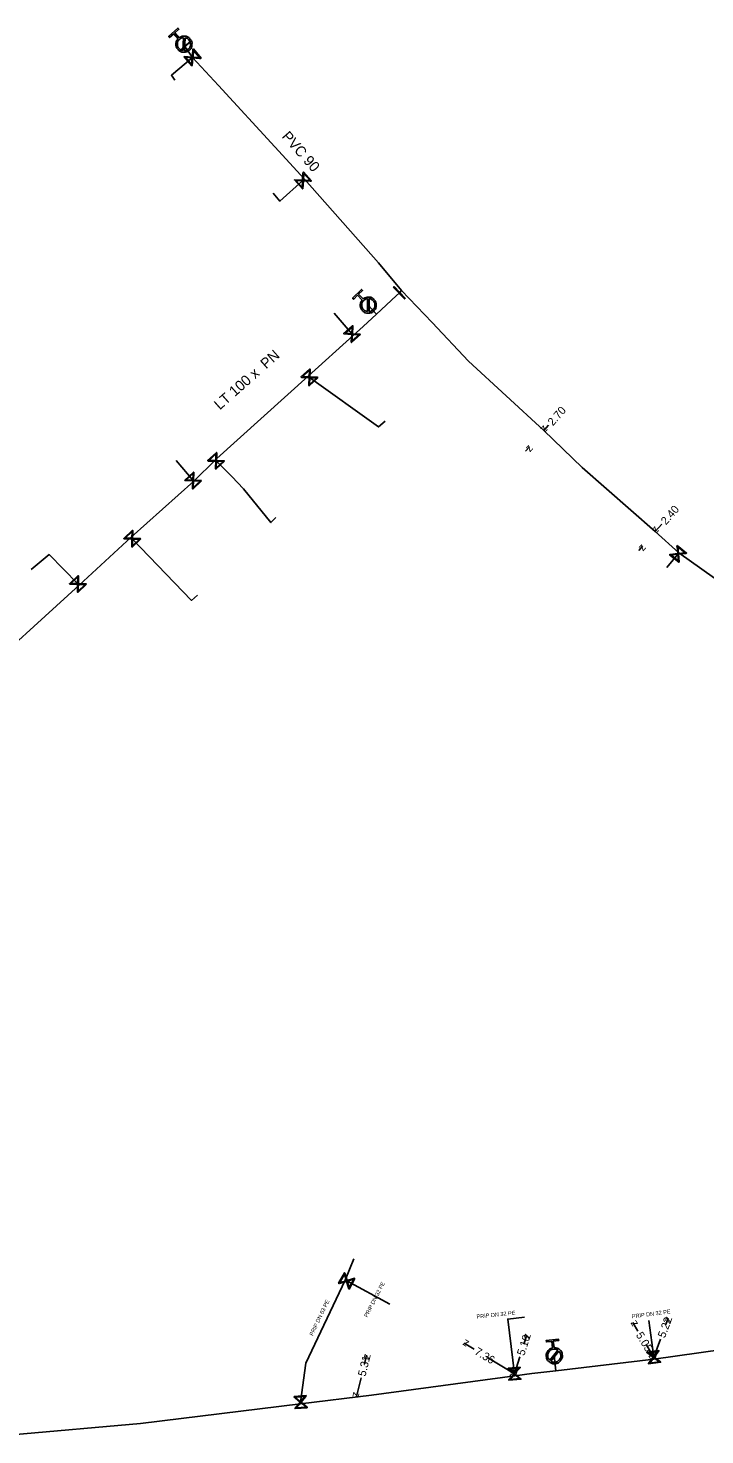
# Model space of a CAD drawing. Extents: x -643842 to -636370, y -1119190 to -1110210.
# Drawn here: x -642219.1 to -642134.5, y -1115188.5 to -1115012.7 of the extents above; entities that cross this region are included whole.
import ezdxf

# ---------------------------------------------------------------- set-up
doc = ezdxf.new("R2010")
doc.units = 0
for name, color, linetype in [('22', 7, 'Continuous'), ('Default', 7, 'Continuous'), ('Level 10', 7, 'Continuous'), ('Level 16', 7, 'Continuous'), ('Level 20', 7, 'Continuous'), ('Level 21', 7, 'Continuous'), ('Level 23', 7, 'Continuous'), ('Level 33', 7, 'Continuous')]:
    doc.layers.add(name, color=color, linetype=linetype)

msp = doc.modelspace()

# ---------------------------------------------------------------- linework, layer by layer
at = {"layer": 'Default'}
for points in [[(-642200.2, -1115013.9), (-642199.91, -1115013.68), (-642199.55, -1115013.7), (-642199.13, -1115013.72), (-642198.86, -1115014.03), (-642198.58, -1115014.34), (-642198.6, -1115014.75), (-642198.62, -1115015.17), (-642198.93, -1115015.44), (-642199.24, -1115015.72), (-642199.65, -1115015.7), (-642200.06, -1115015.68), (-642200.34, -1115015.37), (-642200.62, -1115015.06), (-642200.6, -1115014.65), (-642200.58, -1115014.28), (-642200.34, -1115014.02)], [(-642199.65, -1115013.89), (-642199.93, -1115013.9), (-642200.15, -1115014.1), (-642200.4, -1115014.32), (-642200.42, -1115014.66), (-642200.43, -1115014.99), (-642200.21, -1115015.24), (-642200.01, -1115015.46), (-642199.73, -1115015.5)], [(-642199.55, -1115015.51), (-642199.27, -1115015.5), (-642199.06, -1115015.3), (-642198.81, -1115015.08), (-642198.79, -1115014.74), (-642198.77, -1115014.41), (-642199, -1115014.16), (-642199.19, -1115013.94), (-642199.47, -1115013.9)], [(-642177.19, -1115046.54), (-642176.92, -1115046.31), (-642176.55, -1115046.31), (-642176.14, -1115046.31), (-642175.85, -1115046.61), (-642175.56, -1115046.9), (-642175.56, -1115047.32), (-642175.56, -1115047.73), (-642175.86, -1115048.02), (-642176.15, -1115048.31), (-642176.56, -1115048.31), (-642176.98, -1115048.31), (-642177.27, -1115048.02), (-642177.56, -1115047.72), (-642177.56, -1115047.31), (-642177.56, -1115046.94), (-642177.33, -1115046.67)], [(-642176.65, -1115046.5), (-642176.93, -1115046.53), (-642177.13, -1115046.73), (-642177.37, -1115046.97), (-642177.38, -1115047.31), (-642177.38, -1115047.64), (-642177.14, -1115047.88), (-642176.93, -1115048.09), (-642176.66, -1115048.12)], [(-642176.47, -1115048.12), (-642176.2, -1115048.09), (-642175.99, -1115047.89), (-642175.75, -1115047.65), (-642175.75, -1115047.32), (-642175.75, -1115046.98), (-642175.98, -1115046.74), (-642176.19, -1115046.53), (-642176.46, -1115046.5)], [(-642153.35, -1115177.6), (-642152.99, -1115177.59), (-642152.7, -1115177.81), (-642152.37, -1115178.07), (-642152.32, -1115178.48), (-642152.27, -1115178.89), (-642152.53, -1115179.22), (-642152.78, -1115179.54), (-642153.19, -1115179.59), (-642153.6, -1115179.64), (-642153.93, -1115179.39), (-642154.26, -1115179.14), (-642154.31, -1115178.73), (-642154.36, -1115178.31), (-642154.11, -1115177.99), (-642153.88, -1115177.7), (-642153.53, -1115177.62)], [(-642152.89, -1115177.91), (-642153.13, -1115177.76), (-642153.42, -1115177.79), (-642153.75, -1115177.83), (-642153.96, -1115178.1), (-642154.17, -1115178.36), (-642154.12, -1115178.7), (-642154.09, -1115178.99), (-642153.89, -1115179.18)], [(-642153.74, -1115179.3), (-642153.5, -1115179.44), (-642153.22, -1115179.41), (-642152.88, -1115179.36), (-642152.68, -1115179.1), (-642152.47, -1115178.83), (-642152.51, -1115178.5), (-642152.55, -1115178.21), (-642152.75, -1115178.02)]]:
    msp.add_open_spline(points, degree=3, dxfattribs=at)
at = {"layer": 'Level 10'}
for points in [[(-642154.03, -1115062.33), (-642154.62, -1115062.99)], [(-642156.9, -1115065.58), (-642156.4, -1115065.02)], [(-642139.89, -1115074.7), (-642140.7, -1115075.62)], [(-642142.77, -1115077.98), (-642142.28, -1115077.42)], [(-642139.37, -1115174.71), (-642139.07, -1115173.9)], [(-642157.11, -1115177.15), (-642156.74, -1115176)], [(-642142.86, -1115175.54), (-642143.51, -1115174.47)], [(-642163.33, -1115177.79), (-642164.58, -1115177.03)], [(-642141.84, -1115177.22), (-642140.89, -1115178.79)], [(-642140.04, -1115176.52), (-642140.89, -1115178.79)], [(-642177.04, -1115179.63), (-642176.77, -1115178.54)], [(-642161.66, -1115178.81), (-642158.29, -1115180.86)], [(-642157.62, -1115178.76), (-642158.29, -1115180.86)], [(-642177.46, -1115181.38), (-642178.03, -1115183.7)]]:
    msp.add_lwpolyline(points, dxfattribs=at)
at = {"layer": 'Level 16'}
for points in [[(-642198.9, -1115014.51), (-642200.02, -1115015.52), (-642200.08, -1115015.45), (-642198.96, -1115014.44), (-642198.9, -1115014.51)], [(-642198.43, -1115015.29), (-642197.47, -1115016.44), (-642197.52, -1115016.49), (-642197.64, -1115016.47), (-642198.48, -1115016.4), (-642198.56, -1115017.36), (-642198.61, -1115017.41), (-642199.58, -1115016.26), (-642199.53, -1115016.22), (-642198.56, -1115016.3), (-642198.49, -1115015.47), (-642198.48, -1115015.34), (-642198.43, -1115015.29)], [(-642198.4, -1115015.47), (-642198.47, -1115016.31), (-642197.64, -1115016.38), (-642198.4, -1115015.47)], [(-642198.64, -1115017.23), (-642198.57, -1115016.39), (-642199.41, -1115016.32), (-642198.64, -1115017.23)], [(-642184.67, -1115030.67), (-642183.67, -1115031.78), (-642183.72, -1115031.82), (-642183.84, -1115031.81), (-642184.68, -1115031.77), (-642184.73, -1115032.74), (-642184.78, -1115032.79), (-642185.79, -1115031.67), (-642185.74, -1115031.63), (-642184.77, -1115031.68), (-642184.73, -1115030.84), (-642184.72, -1115030.71), (-642184.67, -1115030.67)], [(-642184.81, -1115032.61), (-642184.77, -1115031.77), (-642185.61, -1115031.73), (-642184.81, -1115032.61)], [(-642184.64, -1115030.85), (-642184.68, -1115031.69), (-642183.84, -1115031.73), (-642184.64, -1115030.85)], [(-642173.32, -1115045), (-642171.95, -1115046.45), (-642172.04, -1115046.54), (-642173.41, -1115045.09), (-642173.32, -1115045)], [(-642177.53, -1115051), (-642178.66, -1115051.99), (-642178.7, -1115051.94), (-642178.69, -1115051.81), (-642178.64, -1115050.97), (-642179.6, -1115050.91), (-642179.65, -1115050.86), (-642178.52, -1115049.87), (-642178.48, -1115049.92), (-642178.54, -1115050.89), (-642177.7, -1115050.94), (-642177.57, -1115050.95), (-642177.53, -1115051)], [(-642179.47, -1115050.83), (-642178.63, -1115050.89), (-642178.58, -1115050.05), (-642179.47, -1115050.83)], [(-642177.71, -1115051.03), (-642178.55, -1115050.98), (-642178.6, -1115051.81), (-642177.71, -1115051.03)], [(-642182.86, -1115056.38), (-642183.96, -1115057.4), (-642184.01, -1115057.35), (-642184, -1115057.22), (-642183.96, -1115056.38), (-642184.93, -1115056.34), (-642184.98, -1115056.29), (-642183.87, -1115055.28), (-642183.83, -1115055.33), (-642183.87, -1115056.3), (-642183.03, -1115056.33), (-642182.9, -1115056.33), (-642182.86, -1115056.38)], [(-642184.8, -1115056.26), (-642183.96, -1115056.29), (-642183.93, -1115055.45), (-642184.8, -1115056.26)], [(-642183.04, -1115056.42), (-642183.87, -1115056.39), (-642183.91, -1115057.22), (-642183.04, -1115056.42)], [(-642194.52, -1115066.8), (-642195.61, -1115067.83), (-642195.65, -1115067.78), (-642195.65, -1115067.65), (-642195.62, -1115066.81), (-642196.59, -1115066.79), (-642196.64, -1115066.74), (-642195.55, -1115065.71), (-642195.51, -1115065.76), (-642195.53, -1115066.73), (-642194.69, -1115066.75), (-642194.56, -1115066.75), (-642194.52, -1115066.8)], [(-642196.46, -1115066.71), (-642195.62, -1115066.73), (-642195.6, -1115065.89), (-642196.46, -1115066.71)], [(-642194.7, -1115066.84), (-642195.54, -1115066.82), (-642195.56, -1115067.65), (-642194.7, -1115066.84)], [(-642197.39, -1115069.27), (-642198.49, -1115070.29), (-642198.54, -1115070.24), (-642198.53, -1115070.11), (-642198.5, -1115069.27), (-642199.47, -1115069.24), (-642199.51, -1115069.19), (-642198.41, -1115068.17), (-642198.36, -1115068.22), (-642198.4, -1115069.19), (-642197.56, -1115069.22), (-642197.44, -1115069.22), (-642197.39, -1115069.27)], [(-642199.33, -1115069.15), (-642198.49, -1115069.19), (-642198.46, -1115068.35), (-642199.33, -1115069.15)], [(-642197.57, -1115069.31), (-642198.41, -1115069.28), (-642198.44, -1115070.11), (-642197.57, -1115069.31)], [(-642205, -1115076.52), (-642206.09, -1115077.56), (-642206.13, -1115077.51), (-642206.13, -1115077.38), (-642206.11, -1115076.54), (-642207.08, -1115076.52), (-642207.12, -1115076.47), (-642206.04, -1115075.44), (-642205.99, -1115075.48), (-642206.02, -1115076.45), (-642205.18, -1115076.47), (-642205.05, -1115076.47), (-642205, -1115076.52)], [(-642206.95, -1115076.43), (-642206.11, -1115076.45), (-642206.09, -1115075.61), (-642206.95, -1115076.43)], [(-642205.18, -1115076.56), (-642206.02, -1115076.54), (-642206.04, -1115077.38), (-642205.18, -1115076.56)], [(-642137.95, -1115077.34), (-642136.78, -1115078.29), (-642136.83, -1115078.34), (-642136.95, -1115078.35), (-642137.79, -1115078.44), (-642137.69, -1115079.4), (-642137.73, -1115079.45), (-642138.9, -1115078.51), (-642138.85, -1115078.46), (-642137.89, -1115078.36), (-642137.97, -1115077.52), (-642137.99, -1115077.4), (-642137.95, -1115077.34)], [(-642137.89, -1115077.52), (-642137.8, -1115078.35), (-642136.97, -1115078.26), (-642137.89, -1115077.52)], [(-642137.79, -1115079.29), (-642137.88, -1115078.45), (-642138.71, -1115078.53), (-642137.79, -1115079.29)], [(-642211.79, -1115082.19), (-642212.88, -1115083.22), (-642212.92, -1115083.17), (-642212.92, -1115083.04), (-642212.9, -1115082.2), (-642213.87, -1115082.18), (-642213.91, -1115082.13), (-642212.82, -1115081.1), (-642212.78, -1115081.15), (-642212.8, -1115082.12), (-642211.96, -1115082.14), (-642211.84, -1115082.14), (-642211.79, -1115082.19)], [(-642213.74, -1115082.1), (-642212.89, -1115082.12), (-642212.87, -1115081.28), (-642213.74, -1115082.1)], [(-642211.97, -1115082.23), (-642212.81, -1115082.21), (-642212.83, -1115083.04), (-642211.97, -1115082.23)], [(-642178.23, -1115168.95), (-642178.95, -1115170.28), (-642179, -1115170.24), (-642179.04, -1115170.12), (-642179.28, -1115169.32), (-642180.21, -1115169.6), (-642180.27, -1115169.56), (-642179.55, -1115168.24), (-642179.5, -1115168.27), (-642179.22, -1115169.21), (-642178.42, -1115168.96), (-642178.29, -1115168.92), (-642178.23, -1115168.95)], [(-642180.11, -1115169.47), (-642179.3, -1115169.23), (-642179.55, -1115168.43), (-642180.11, -1115169.47)], [(-642178.39, -1115169.05), (-642179.19, -1115169.29), (-642178.95, -1115170.09), (-642178.39, -1115169.05)], [(-642141.74, -1115178.15), (-642140.25, -1115177.94), (-642140.24, -1115178.01), (-642140.32, -1115178.11), (-642140.83, -1115178.78), (-642140.05, -1115179.36), (-642140.04, -1115179.43), (-642141.53, -1115179.64), (-642141.54, -1115179.57), (-642140.95, -1115178.8), (-642141.62, -1115178.29), (-642141.73, -1115178.22), (-642141.74, -1115178.15)], [(-642141.57, -1115178.22), (-642140.9, -1115178.73), (-642140.39, -1115178.06), (-642141.57, -1115178.22)], [(-642140.21, -1115179.36), (-642140.88, -1115178.85), (-642141.38, -1115179.52), (-642140.21, -1115179.36)], [(-642159.1, -1115180.17), (-642157.6, -1115180.05), (-642157.6, -1115180.12), (-642157.68, -1115180.21), (-642158.23, -1115180.85), (-642157.49, -1115181.48), (-642157.48, -1115181.55), (-642158.98, -1115181.67), (-642158.98, -1115181.6), (-642158.35, -1115180.86), (-642158.99, -1115180.32), (-642159.09, -1115180.24), (-642159.1, -1115180.17)], [(-642158.93, -1115180.25), (-642158.29, -1115180.8), (-642157.75, -1115180.16), (-642158.93, -1115180.25)], [(-642157.64, -1115181.47), (-642158.28, -1115180.92), (-642158.83, -1115181.56), (-642157.64, -1115181.47)], [(-642185.83, -1115183.72), (-642184.33, -1115183.6), (-642184.33, -1115183.67), (-642184.41, -1115183.76), (-642184.96, -1115184.4), (-642184.22, -1115185.03), (-642184.21, -1115185.1), (-642185.71, -1115185.22), (-642185.71, -1115185.15), (-642185.08, -1115184.41), (-642185.72, -1115183.87), (-642185.82, -1115183.79), (-642185.83, -1115183.72)], [(-642185.66, -1115183.8), (-642185.02, -1115184.35), (-642184.48, -1115183.71), (-642185.66, -1115183.8)], [(-642184.37, -1115185.02), (-642185.01, -1115184.47), (-642185.56, -1115185.11), (-642184.37, -1115185.02)]]:
    msp.add_lwpolyline(points, dxfattribs=at)
at = {"layer": 'Level 21'}
for points in [[(-642198.52, -1115016.35), (-642195.28, -1115019.88), (-642188.24, -1115027.53), (-642184.54, -1115031.55), (-642175.29, -1115042.01), (-642172.41, -1115045.49)], [(-642226.44, -1115094.82), (-642212.72, -1115082.29), (-642206.19, -1115076.32), (-642198.38, -1115069.31), (-642195.67, -1115066.64), (-642195.5, -1115066.48), (-642184.07, -1115056.18), (-642178.44, -1115051.11), (-642177.21, -1115050), (-642175.54, -1115048.45), (-642173.06, -1115046.13), (-642172.68, -1115045.77), (-642172.41, -1115045.49)], [(-642096.47, -1115104.33), (-642099.41, -1115102.55), (-642107.92, -1115097.4), (-642112.86, -1115094.41), (-642116.46, -1115092.07), (-642120.42, -1115089.63), (-642126.07, -1115086.15), (-642130.4, -1115083.48), (-642137.77, -1115078.28), (-642140.7, -1115075.62), (-642149.85, -1115067.62), (-642154.62, -1115062.99), (-642164.03, -1115054.31), (-642168.6, -1115049.5), (-642172.41, -1115045.49)], [(-641973.55, -1115156.85), (-641975.56, -1115157.26), (-641999.1, -1115160.18), (-642022.03, -1115163.25), (-642035.96, -1115165.14), (-642057.58, -1115168.08), (-642083.46, -1115171.53), (-642087.27, -1115172.03), (-642105.03, -1115174.46), (-642122.74, -1115176.48), (-642123.7, -1115176.62), (-642140.86, -1115179.04), (-642153.13, -1115180.49), (-642156.12, -1115180.85), (-642158.26, -1115181.11), (-642176.15, -1115183.52), (-642185.05, -1115184.62), (-642205.03, -1115187.09), (-642221.08, -1115188.5), (-642223.2, -1115186.19), (-642228.27, -1115181.15), (-642229.1, -1115180.38), (-642229.73, -1115179.82)]]:
    msp.add_lwpolyline(points, dxfattribs=at)
at = {"layer": 'Level 23'}
for points in [[(-642198.52, -1115016.35), (-642199.49, -1115014.98), (-642199.6, -1115014.7)], [(-642198.52, -1115016.35), (-642201.18, -1115018.58), (-642200.76, -1115019.19)], [(-642184.54, -1115031.55), (-642184.73, -1115031.73), (-642187.6, -1115034.33), (-642188.46, -1115033.32)], [(-642176.56, -1115047.31), (-642175.54, -1115048.45)], [(-642178.44, -1115051.11), (-642178.59, -1115050.93), (-642180.83, -1115048.33)], [(-642184.07, -1115056.18), (-642183.92, -1115056.34), (-642175.27, -1115062.53), (-642174.44, -1115061.8)], [(-642198.38, -1115069.31), (-642198.45, -1115069.23), (-642200.59, -1115066.74)], [(-642195.67, -1115066.64), (-642195.58, -1115066.77), (-642193.62, -1115068.73), (-642192.14, -1115070.27), (-642188.73, -1115074.48), (-642188.1, -1115073.85)], [(-642206.19, -1115076.32), (-642206.06, -1115076.5), (-642198.65, -1115084.21), (-642197.92, -1115083.56)], [(-642212.72, -1115082.29), (-642212.85, -1115082.16), (-642216.43, -1115078.49), (-642218.71, -1115080.33)], [(-642137.77, -1115078.28), (-642137.84, -1115078.4), (-642139.25, -1115080.08)], [(-642178.36, -1115166.5), (-642179.45, -1115169.15), (-642184.38, -1115179.54), (-642185.02, -1115184.41), (-642185.05, -1115184.62)], [(-642179.45, -1115169.15), (-642179.25, -1115169.26), (-642173.86, -1115172.16)], [(-642158.26, -1115181.11), (-642158.29, -1115180.86), (-642159.14, -1115174.03), (-642157.02, -1115173.81)], [(-642140.86, -1115179.04), (-642140.89, -1115178.79), (-642141.49, -1115174.21)], [(-642153.32, -1115178.6), (-642153.13, -1115180.49)]]:
    msp.add_lwpolyline(points, dxfattribs=at)
at = {"layer": 'Level 33'}
for points in [[(-642200.34, -1115014.02), (-642200.88, -1115013.41), (-642201.4, -1115013.88), (-642201.52, -1115013.74), (-642200.36, -1115012.69), (-642200.24, -1115012.83), (-642200.75, -1115013.29), (-642200.2, -1115013.9)], [(-642199.73, -1115015.5), (-642199.65, -1115013.89)], [(-642199.47, -1115013.9), (-642199.55, -1115015.51)], [(-642177.33, -1115046.67), (-642177.9, -1115046.08), (-642178.39, -1115046.57), (-642178.52, -1115046.44), (-642177.41, -1115045.34), (-642177.28, -1115045.47), (-642177.77, -1115045.95), (-642177.19, -1115046.54)], [(-642176.66, -1115048.12), (-642176.65, -1115046.5)], [(-642176.46, -1115046.5), (-642176.47, -1115048.12)], [(-642153.53, -1115177.62), (-642153.63, -1115176.81), (-642154.31, -1115176.89), (-642154.34, -1115176.71), (-642152.79, -1115176.52), (-642152.76, -1115176.7), (-642153.45, -1115176.79), (-642153.35, -1115177.6)], [(-642153.89, -1115179.18), (-642152.89, -1115177.91)], [(-642152.75, -1115178.02), (-642153.74, -1115179.3)]]:
    msp.add_lwpolyline(points, dxfattribs=at)

# ---------------------------------------------------------------- texts
at = {"layer": '22'}
for s, rotation, p in [('PRIP DN 32 PE', 63.0485, (-642176.67, -1115173.87)), ('PRIP DN 63 PE', 64.5981, (-642183.49, -1115176.17)), ('PRIP DN 32 PE', 5.8498, (-642163.01, -1115173.97)), ('PRIP DN 32 PE', 7.5192, (-642143.59, -1115173.95))]:
    msp.add_text(s, height=0.5, rotation=rotation, dxfattribs=at).set_placement(p)
at = {"layer": 'Level 10'}
for s, rotation, p in [('2.70', 48.6484, (-642153.49, -1115062.47)), ('z', 228.6484, (-642154.66, -1115062.29)), ('z', 48.6484, (-642156.36, -1115065.73)), ('2.40', 48.7153, (-642139.35, -1115074.84)), ('z', 228.7153, (-642140.74, -1115074.91)), ('z', 48.7153, (-642142.23, -1115078.13)), ('z', 121.236, (-642142.82, -1115174.64)), ('5.22', 69.5853, (-642139.49, -1115176.46)), ('z', 69.5853, (-642138.78, -1115174.54)), ('5.10', 72.3109, (-642157.07, -1115178.67)), ('z', 72.3109, (-642156.42, -1115176.63)), ('5.05', 301.2361, (-642143.16, -1115176.01)), ('z', 148.6627, (-642163.89, -1115176.86)), ('7.36', 328.6626, (-642163.37, -1115178.35)), ('5.31', 76.2751, (-642176.92, -1115181.26)), ('z', 76.2751, (-642176.4, -1115179.14)), ('z', 301.236, (-642141.58, -1115178.62)), ('z', 249.5853, (-642141.18, -1115178.15)), ('z', 328.6626, (-642158.98, -1115181.03)), ('z', 252.311, (-642158.61, -1115180.23)), ('z', 256.2752, (-642178.4, -1115183.09))]:
    msp.add_text(s, height=1, rotation=rotation, dxfattribs=at).set_placement(p)
at = {"layer": 'Level 20'}
for s, rotation, p in [('PVC 90', 311.487, (-642187.45, -1115026.29)), ('LT 100 x  PN ', 41.493, (-642195.13, -1115060.47))]:
    msp.add_text(s, height=1.3, rotation=rotation, dxfattribs=at).set_placement(p)

doc.saveas('drawing.dxf')
